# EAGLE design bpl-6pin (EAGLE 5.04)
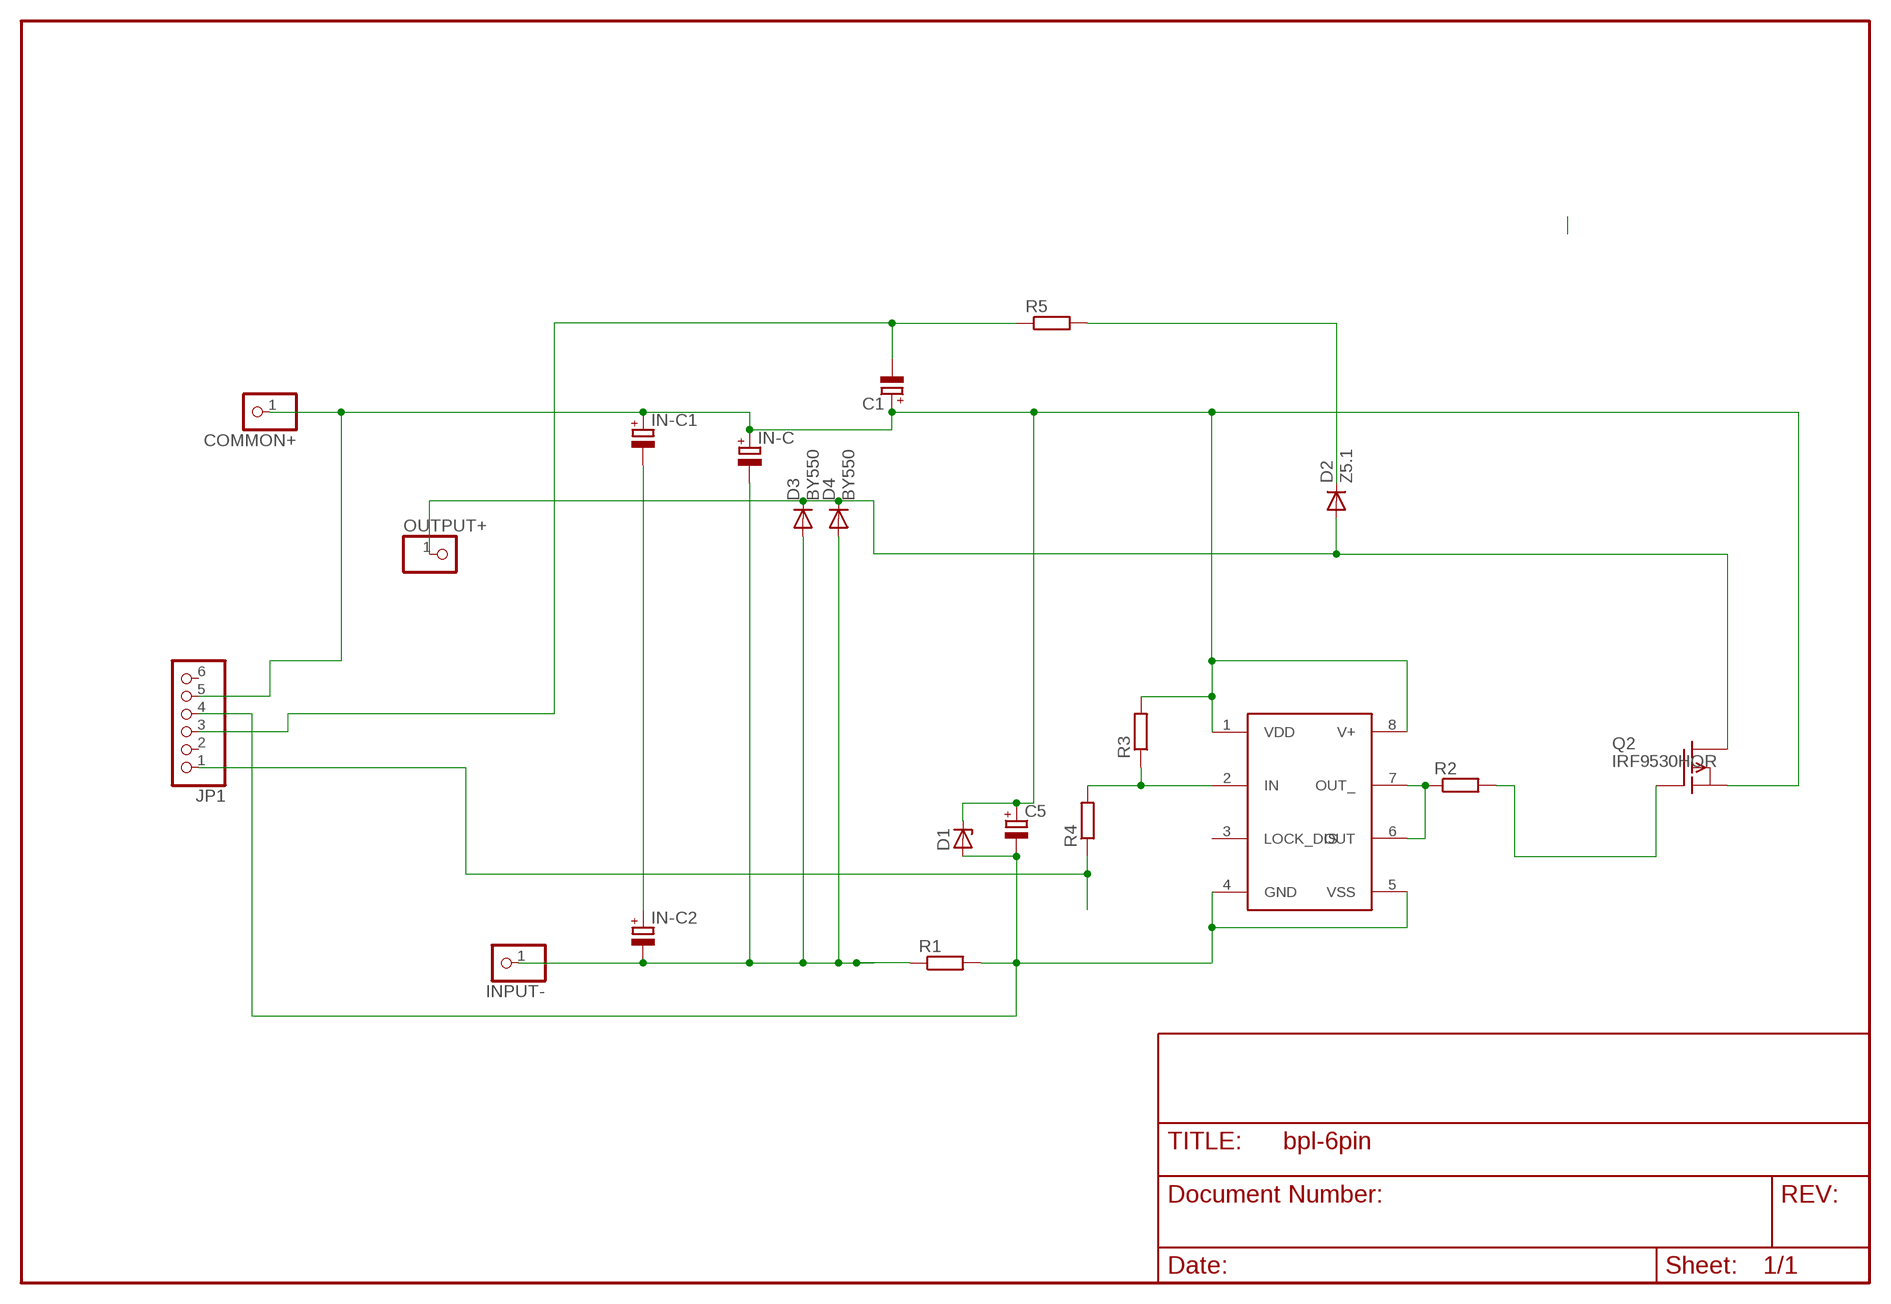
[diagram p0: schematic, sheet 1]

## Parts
C1  CPOL-EUE5-6  [E5-6]
C5  CPOL-EUE2-4  [E2-4]
COMMON+  PINHD-1X1  [1X01]
D1  ZENER-DIODEZD-2.5  [ZDIO-2.5]
D2  Z5.1  DIODE-DO35-10  [DO35-10]
D3  BY550  [DO27-15]
D4  BY550  [DO27-15]
IC1  TC4432X  [SO-08]
IN-C  CPOL-EUE5-8.5  [E5-8,5]
IN-C1  CPOL-EUE2.5-5  [E2,5-5]
IN-C2  CPOL-EUE2.5-5  [E2,5-5]
INPUT-  PINHD-1X1  [1X01]
JP1  PINHD-1X6  [1X06]
OUTPUT+  PINHD-1X1  [1X01]
Q2  IRF9530HOR  [TO220]
R1  R-EU_0207/12  [0207/12]
R2  R-EU_R1206  [R1206]
R3  R-EU_R1206  [R1206]
R4  R-EU_R1206  [R1206]
R5  R-EU_R1206  [R1206]

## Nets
GND: C5.- D1.A IC1.4(GND) IC1.5(VSS) JP1.4 R1.2
N$1: IC1.2(IN) R3.1 R4.2
N$2: C1.- JP1.3 R5.1
N$3: IC1.6(OUT) IC1.7(OUT_) R2.1
N$4: IN-C1.- IN-C2.+
N$5: D2.C R5.2
N$6: Q2.1(G) R2.2
N$9: D3.A D4.A IN-C2.- IN-C.- INPUT-.1 R1.1
N$10: D2.A D3.C D4.C OUTPUT+.1 Q2.2(D)
N$11: JP1.1 R4.1
VDD: C1.+ C5.+ COMMON+.1 D1.C IC1.1(VDD) IC1.8(V+) IN-C1.+ IN-C.+ JP1.5 Q2.3(S) R3.2
Unconnected: IC1.3(LOCK_DIS) JP1.2 JP1.6

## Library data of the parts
C1 C5 IN-C IN-C1 IN-C2 = rcl(2):CPOL-EU: POLARIZED CAPACITOR, European symbol
COMMON+ INPUT- OUTPUT+ = pinhead:PINHD-1X1: PIN HEADER
D1 = diode-1:ZENER-DIODE: Z-Diode
D2 = diode:DIODE-: DIODE
D3 D4 = diode-1:BY550: DIODE
IC1 = microchip:TC4432
JP1 = pinhead:PINHD-1X6: PIN HEADER
Q2 = transistor-fet:IRF9530: P-Channel Enhancement MOSFET (HEXFET); -100V; -12A; 0,3Ohm
R1-R5 = rcl-2:R-EU_: RESISTOR, European symbol

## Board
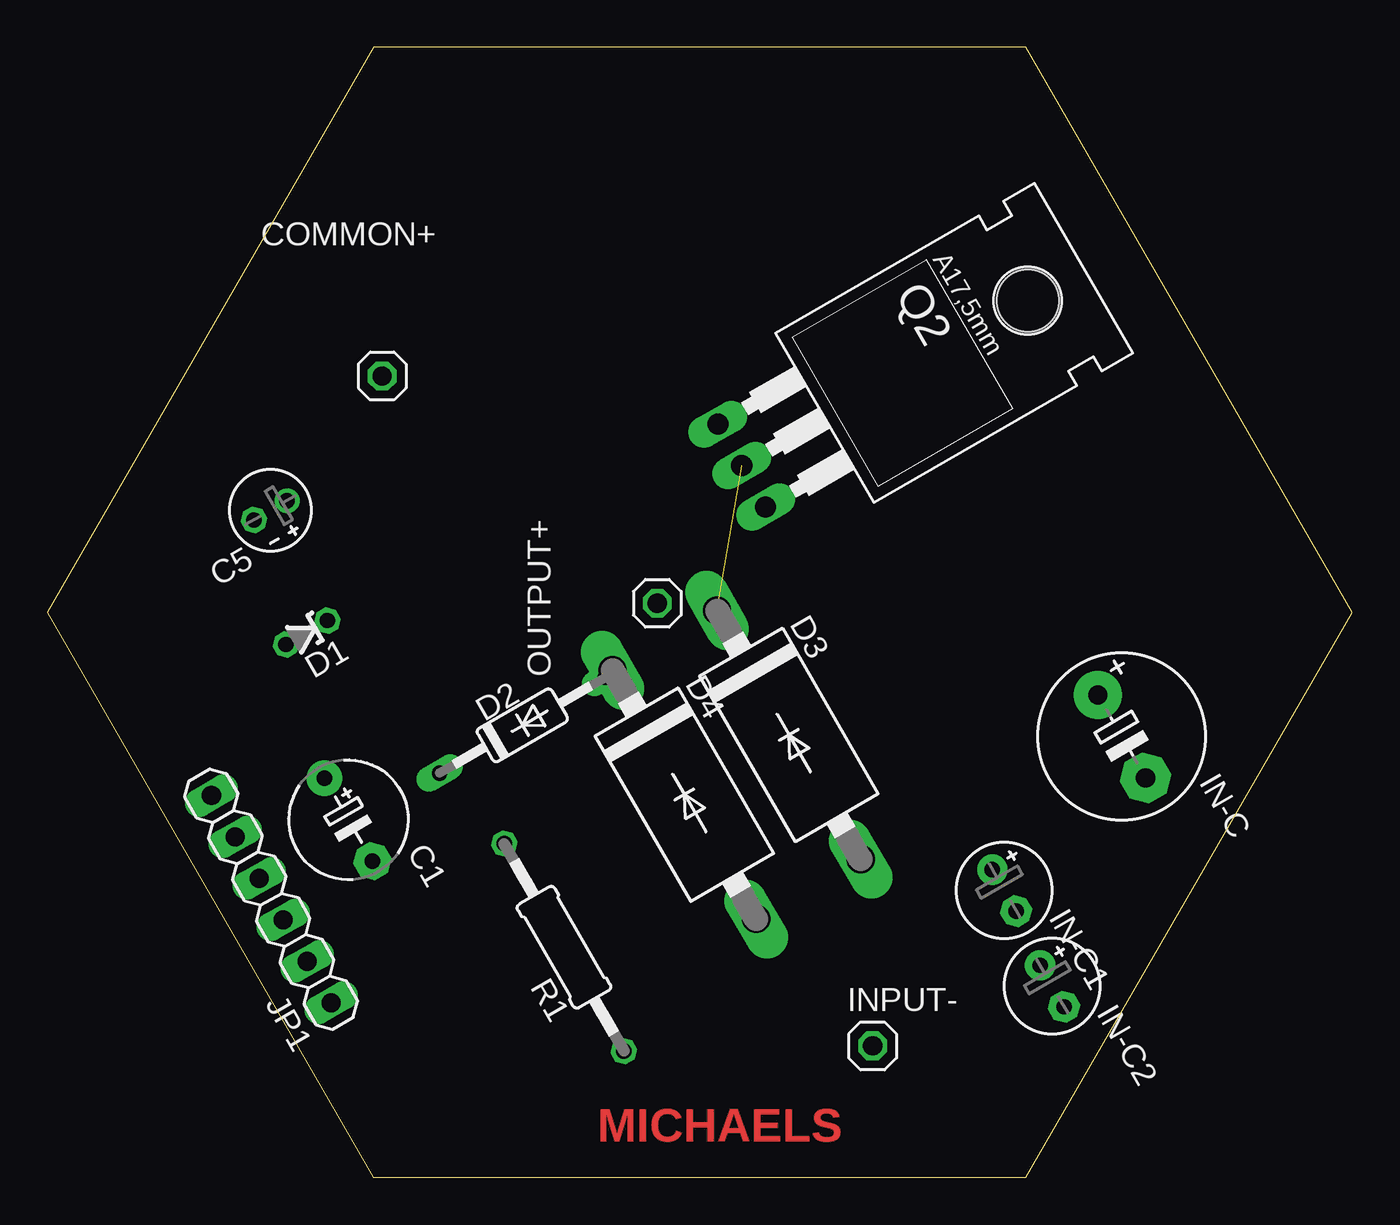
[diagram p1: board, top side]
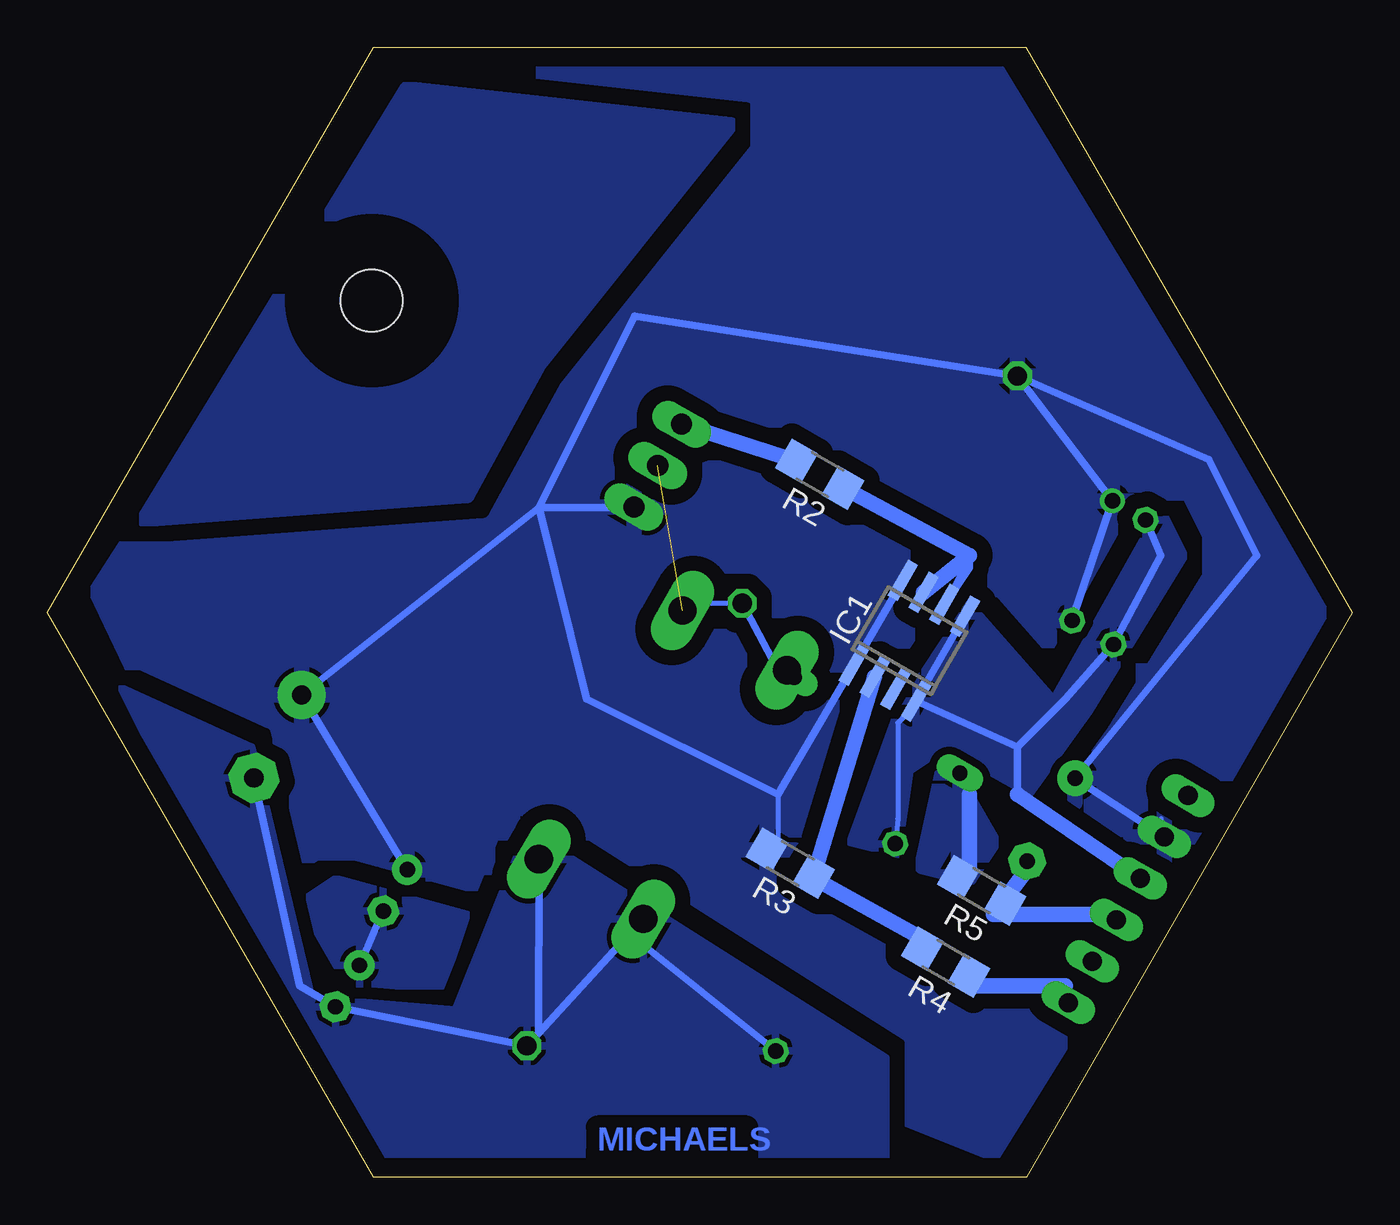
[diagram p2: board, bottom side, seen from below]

Size 69.28 x 60 mm. Coordinates in mm from the lower left corner, seen from the top.
Outline: 17.31,0 51.96,0 69.28,30 51.96,60 17.32,60 0,30 17.31,0
Copper layers (1*16): Top 0.035mm / dielectric 1.5mm / Bottom 0.035mm
Design rules "default": minimum track width 10mil, minimum drill 24mil, track to track 8mil, track to pad 8mil, pad to pad 8mil, via to via 8mil, smd to smd 8mil, copper to edge 40mil, drill to drill 8mil, minimum pad ring 10mil, minimum via ring 8mil, stop-mask expansion 4mil, vias tented up to drill 0mil, thermal gap 10mil

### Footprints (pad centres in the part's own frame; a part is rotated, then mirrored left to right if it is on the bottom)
E5-6 = drill 0.813 pad 1.905 round: + -2.54,0 | drill 0.813 pad 1.905 octagon: - 2.54,0
E2-4 = drill 0.813 pad 1.27 round: + -1.016,0 | drill 0.813 pad 1.27 octagon: - 1.016,0
1X01 = drill 1.016 octagon: 1 0,0
ZDIO-2.5 = drill 0.813 octagon: A 1.27,0; C -1.27,0
DO35-10 = drill 0.813 long: A 5.08,0; C -5.08,0
DO27-15 = drill 1.499 long: A 7.62,0; C -7.62,0
SO-08 = smd 0.6 x 2.2: 1 -1.905,-2.6; 2 -0.635,-2.6; 3 0.635,-2.6; 4 1.905,-2.6; 5 1.905,2.6; 6 0.635,2.6; 7 -0.635,2.6; 8 -1.905,2.6
E5-8,5 = drill 1.016 pad 2.54 round: + -2.54,0 | drill 1.016 pad 2.54 octagon: - 2.54,0
E2,5-5 = drill 0.813 pad 1.6 round: + -1.27,0 | drill 0.813 pad 1.6 octagon: - 1.27,0
1X06 = drill 1.016 long: 1 -6.35,0; 2 -3.81,0; 3 -1.27,0; 4 1.27,0; 5 3.81,0; 6 6.35,0
TO220 = drill 1.118 long: 1 -2.54,-6.35; 2 0,-6.35; 3 2.54,-6.35 | hole 3.302: 0,11.176
0207/12 = drill 0.813 octagon: 1 -6.35,0; 2 6.35,0
R1206 = smd 1.6 x 1.803: 1 -1.422,0; 2 1.422,0

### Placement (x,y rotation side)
C1  15.99,18.99 300 top
C5  11.85,35.41 210 top
COMMON+  17.78,42.55 0 top
D1  13.78,28.93 210 top
D2  25.23,24 30 top
D3  39.37,23.5 300 top
D4  33.83,20.32 300 top
IC1  23.51,28.49 330 bottom
IN-C  57.03,23.41 300 top
IN-C1  50.8,15.24 300 top
IN-C2  53.34,10.16 300 top
INPUT-  43.81,6.99 0 top
JP1  11.89,14.78 120 top
OUTPUT+  32.38,30.48 0 top
Q2  42.37,40.96 300 top
R1  27.44,12.22 120 top
R2  28.27,37.33 150 bottom
R3  29.84,16.68 150 bottom
R4  21.59,11.43 150 bottom
R5  19.68,15.24 150 bottom

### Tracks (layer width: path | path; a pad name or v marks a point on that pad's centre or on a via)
GND
  Bottom 0.254: R1.2 24.13,19.05 24.13,24.13 22.86,25.4 IC1.4
  Bottom 0.406: C5.- 10.16,33.02 D1.A 15.24,25.4 17.78,22.86 | 17.78,20.32 17.78,22.86 | 17.78,22.86 IC1.4 IC1.5
  Bottom 0.813: JP1.4 17.78,20.32
  pour Bottom (isolate 0.406): 10.16,35.56 8.89,33.02 13.97,24.77 17.14,20.32 21.59,22.86 23.5,21.59 24.13,17.14 26.67,17.78 24.13,24.77 20.32,30.48 15.88,25.4
N$1
  Bottom 0.254: R4.2 22.86,12.7 | 28.57,15.88 28.05,17.81
  Bottom 0.813: R3.1 28.05,17.81 IC1.2 | 22.86,12.7 28.57,15.88
N$2
  Bottom 0.254: 17.14,16.51 C1.- | JP1.3 12.7,13.97 | 19.05,13.97 R5.1
  Bottom 0.813: 17.14,16.51 19.05,13.97 12.7,13.97
N$3
  Bottom 0.254: 20.32,33.02 21.59,30.48 IC1.6
  Bottom 0.406: 20.32,33.02 20.32,32.38 IC1.6
  Bottom 0.813: R2.1 20.32,33.02 IC1.7
N$4
  Bottom 0.406: IN-C2.+ IN-C1.-
  pour Bottom (isolate 0.61, rank 2): 53.34,10.16 48.26,10.16 46.99,13.97 53.98,15.88 55.88,14.61
N$5
  Bottom 0.254: R5.2 20.32,16.51 | 20.32,20.32 D2.C
  Bottom 0.813: 20.32,16.51 20.32,20.32
  pour Bottom (isolate 0.406, rank 3): 21.59,22.23 22.86,16.51 20.32,15.88 19.05,17.78
N$6
  Bottom 0.813: R2.2 Q2.1
N$8
  pour Bottom (isolate 0.406, rank 2): 33.02,55.88 43.18,43.18 46.99,36.2 64.14,34.92 50.16,57.78
N$9
  Bottom 0.406: IN-C.- 55.88,10.16 IN-C2.- INPUT-.1 43.21,7.65 | 38.36,12.94 D4.A | 38.36,12.94 43.21,7.65 | 43.21,7.65 D3.A | R1.1 38.36,12.94
  pour Bottom (isolate 0.61): 24.77,6.35 43.81,18.41 47.62,8.89 55.24,9.53 58.42,22.86 65.41,26.04 52.7,0.64 24.77,0.64
N$10  (1 unrouted)
  Bottom 0.254: D4.C 30.48,26.67 30.39,26.72 | OUTPUT+.1 34.29,30.48 D3.C
  Bottom 0.406: D2.A 30.39,26.72 OUTPUT+.1
N$11
  Bottom 0.254: 20.32,10.16 R4.1 | JP1.1 15.24,10.16
  Bottom 0.813: 15.24,10.16 20.32,10.16
VDD
  Bottom 0.254: 30.48,20.32 30.48,17.78 R3.2 | JP1.5 10.16,19.05 | 39.37,35.56 Q2.3
  Bottom 0.406: JP1.5 C1.+ 5.08,33.02 7.62,38.1 COMMON+.1 | COMMON+.1 C5.+ D1.C | 43.18,35.56 IN-C.+ IN-C1.+ | 43.18,35.56 38.1,45.72 COMMON+.1 | IC1.8 IC1.1 30.48,20.32 40.64,25.4 43.18,35.56 | 43.18,35.56 39.37,35.56
  pour Bottom (isolate 0.813, rank 6): 19.05,59.05 1.27,29.84 19.05,1.27 60.33,17.78 66.67,31.11 48.26,59.69

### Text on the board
Top: MICHAELS
Bottom: MICHAELS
